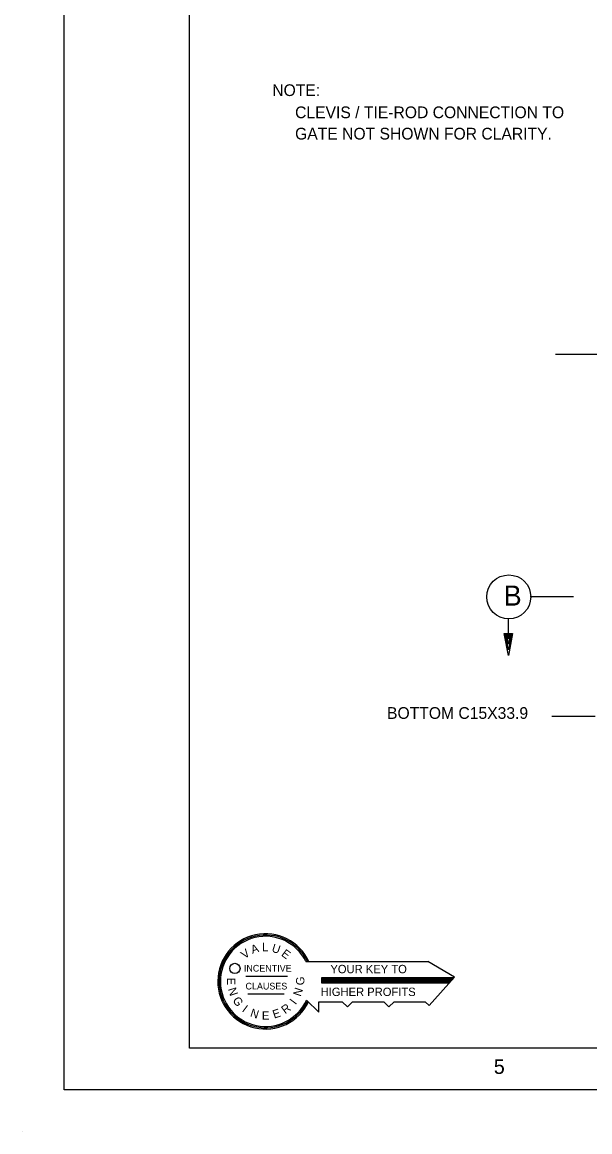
# Model space of a CAD drawing. Extents: x -0.2 to 13.5, y -0.2 to 9.5.
# Drawn here: x -0.167 to 2.095, y -0.167 to 4.255 of the extents above; entities that cross this region are included whole.
import ezdxf

# ---------------------------------------------------------------- set-up
doc = ezdxf.new("R2010")
doc.units = 0
for name, color, linetype in [('Level 1', 7, 'Continuous'), ('Level 2', 7, 'Continuous'), ('Level 25', 7, 'Continuous'), ('Level 3', 7, 'Continuous')]:
    doc.layers.add(name, color=color, linetype=linetype)

msp = doc.modelspace()

# ---------------------------------------------------------------- linework, layer by layer
at = {"layer": 'Level 1'}
for p, q in [((0.9642, 0.5118), (1.4498, 0.5118)), ((1.5558, 0.4492), (1.4498, 0.5118)), ((0.7242, 0.4535), (0.8905, 0.4535)), ((1.5545, 0.4475), (1.0258, 0.4475)), ((1.0258, 0.4475), (1.0258, 0.4268)), ((1.5558, 0.4492), (1.4548, 0.3362)), ((1.5492, 0.4418), (1.0258, 0.4418)), ((1.5445, 0.4365), (1.0258, 0.4365)), ((1.5395, 0.4308), (1.0258, 0.4308)), ((1.0258, 0.4268), (1.5358, 0.4268)), ((0.7328, 0.3832), (0.8768, 0.3832)), ((0.9665, 0.3585), (1.0148, 0.3102)), ((1.0148, 0.3102), (1.0148, 0.3518)), ((1.0148, 0.3518), (1.1085, 0.3518)), ((1.1085, 0.3518), (1.1292, 0.3312)), ((1.1292, 0.3312), (1.1498, 0.3518)), ((1.1498, 0.3518), (1.2738, 0.3518)), ((1.2738, 0.3518), (1.2945, 0.3312)), ((1.2945, 0.3312), (1.3152, 0.3518)), ((1.3152, 0.3518), (1.4392, 0.3518)), ((1.4392, 0.3518), (1.4548, 0.3362))]:
    msp.add_line(p, q, dxfattribs=at)
for points in [[(0, 9.3333), (13.3333, 9.3333), (13.3333, 0), (0, 0)], [(0.5, 9.1667), (13.1667, 9.1667), (13.1667, 0.1667), (0.5, 0.1667)]]:
    msp.add_lwpolyline(points, close=True, dxfattribs=at)
msp.add_circle((0.681, 0.4843), 0.0205, dxfattribs=at)
for radius, start, end in [(0.19, 24.569, 334.4243), (0.1848, 25.3095, 334.4522), (0.1796, 26.0896, 335.5943)]:
    msp.add_arc((0.8028, 0.4328), radius, start, end, dxfattribs=at)
at = {"layer": 'Level 2'}
msp.add_line((1.9438, 1.4899), (2.1164, 1.4899), dxfattribs=at)
at = {"layer": 'Level 25'}
msp.add_line((2.3332, 2.9306), (1.9581, 2.9306), dxfattribs=at)
at = {"layer": 'Level 3'}
for p, q in [((2.0302, 1.9653), (1.8581, 1.9653)), ((1.7708, 1.8195), (1.7708, 1.8778)), ((-0.1667, -0.1667), (-0.1667, -0.1667))]:
    msp.add_line(p, q, dxfattribs=at)
msp.add_lwpolyline([(1.783, 1.8195), (1.7874, 1.8195), (1.7708, 1.732), (1.7544, 1.8195), (1.783, 1.8195), (1.771, 1.7543), (1.7594, 1.8153), (1.7782, 1.8153), (1.771, 1.7763), (1.7645, 1.8112), (1.7733, 1.8112), (1.771, 1.7986), (1.7695, 1.8069)], dxfattribs=at)
msp.add_circle((1.7724, 1.9653), 0.0875, dxfattribs=at)

# ---------------------------------------------------------------- texts
at = {"layer": 'Level 1'}
for s, rotation, p in [('A', 18.0731, (0.7508, 0.5422)), ('U', 342.1107, (0.8252, 0.5518)), ('V', 35.9204, (0.7198, 0.5208)), ('E', 323.9298, (0.8632, 0.5368)), ('E', 270, (0.6492, 0.4475)), ('G', 90, (0.9578, 0.4175)), ('N', 288.0821, (0.6528, 0.4022)), ('N', 71.9179, (0.9432, 0.3705)), ('G', 306.0537, (0.6698, 0.3568)), ('I', 53.5836, (0.9225, 0.3378)), ('I', 323.5836, (0.7068, 0.3145)), ('N', 341.9179, (0.7395, 0.2935)), ('E', 18.2241, (0.8375, 0.2842)), ('R', 36.2206, (0.8812, 0.3012))]:
    msp.add_text(s, height=0.0333, rotation=rotation, dxfattribs=at).set_placement(p)
for s, height, p in [('L', 0.0333, (0.7892, 0.5532)), ('INCENTIVE', 0.02667, (0.7168, 0.4718)), ('YOUR KEY TO', 0.033333, (1.0615, 0.4652)), ('CLAUSES', 0.02667, (0.7232, 0.4005)), ('HIGHER PROFITS', 0.033333, (1.0225, 0.3745)), ('E', 0.0333, (0.7885, 0.2805)), ('5', 0.0584, (1.7128, 0.064))]:
    msp.add_text(s, height=height, dxfattribs=at).set_placement(p)
at = {"layer": 'Level 2'}
for s, height, p in [('NOTE:', 0.0467, (0.8299, 3.9612)), ('CLEVIS / TIE-ROD CONNECTION TO', 0.046698, (0.9208, 3.8729)), ('GATE NOT SHOWN FOR CLARITY.', 0.046698, (0.9208, 3.7879)), ('B', 0.08, (1.7522, 1.9303)), ('BOTTOM C15X33.9', 0.046698, (1.2872, 1.479))]:
    msp.add_text(s, height=height, dxfattribs=at).set_placement(p)

doc.saveas('drawing.dxf')
